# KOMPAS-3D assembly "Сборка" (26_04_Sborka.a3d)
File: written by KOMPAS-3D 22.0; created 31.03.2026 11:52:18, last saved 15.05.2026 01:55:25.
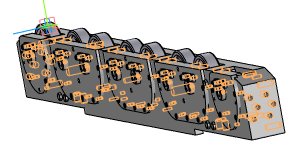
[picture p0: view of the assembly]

Document properties: Автор: taras; Полное имя файла: E:\test_kompas\all_v20\26_04_Sborka.a3d

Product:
- Component [detail]: Деталь  | qty 1  | pos. 2  | Масса: 261.985445; source file: ..\all_v22\3.1.8 дет.45 Балка(оригинал) (1).m3d
- Component [detail]: Деталь  | qty 1  | pos. 3  | Масса: 21.934157; Организация: TMK; Автор: TMK; source file: ..\all_v22\3.1.8  дет.46.2 Крышка балки (2).m3d
- Component [detail]: Деталь  | qty 1  | pos. 4  | Масса: 21.934157; Организация: TMK; Автор: TMK; source file: ..\all_v22\3.1.8  дет.46.2 Крышка балки (2).m3d
- Component [detail]: Деталь  | qty 1  | pos. 5  | Масса: 9.688835; source file: ..\all_v22\Крышка балки 1 окончательная (3).m3d
- Component [detail]: Деталь  | qty 1  | pos. 6  | Масса: 2.046242; Организация: TMK; Автор: TMK; source file: ..\all_v22\3.1.8 дет.74 Ось кронштейна крепления опорного ролика(новый блок) (1).m3d
- Component [detail]: Деталь  | qty 1  | pos. 7  | Масса: 2.046242; Организация: TMK; Автор: TMK; source file: ..\all_v22\3.1.8 дет.74 Ось кронштейна крепления опорного ролика(новый блок) (1).m3d
- Component [detail]: Деталь  | qty 1  | pos. 8  | Масса: 2.046242; Организация: TMK; Автор: TMK; source file: ..\all_v22\3.1.8 дет.74 Ось кронштейна крепления опорного ролика(новый блок) (1).m3d
- Component [detail]: Деталь  | qty 1  | pos. 12  | Масса: 19.948382; Автор: taras; source file: ..\all_v22\05.04 крышка200.m3d
- Component [detail]: Деталь  | qty 1  | pos. 13  | Масса: 2.046242; Организация: TMK; Автор: TMK; source file: ..\all_v22\3.1.8 дет.74 Ось кронштейна крепления опорного ролика(новый блок) (1).m3d
- Component [detail]: Деталь  | qty 1  | pos. 14  | Масса: 2.046242; Организация: TMK; Автор: TMK; source file: ..\all_v22\3.1.8 дет.74 Ось кронштейна крепления опорного ролика(новый блок) (1).m3d
- Component [detail]: Деталь  | qty 1  | pos. 15  | Масса: 9.688835; source file: ..\all_v22\Крышка балки 1 окончательная (3).m3d
- Component [detail]: Деталь  | qty 1  | pos. 16  | Масса: 2.046242; Организация: TMK; Автор: TMK; source file: ..\all_v22\3.1.8 дет.74 Ось кронштейна крепления опорного ролика(новый блок) (1).m3d
- Component [standard]: Винт М10-6gx20 ГОСТ 11738-84  | qty 31  | pos. 17  | Масса: 0.02351; Раздел спецификации: Стандартные изделия; Рассекать на разрезах: no
- Component [detail]: Деталь  | qty 1  | pos. 19  | Масса: 2.046242; Организация: TMK; Автор: TMK; source file: ..\all_v22\3.1.8 дет.74 Ось кронштейна крепления опорного ролика(новый блок) (1).m3d
- Component [detail]: Деталь  | qty 1  | pos. 20  | Масса: 2.046242; Организация: TMK; Автор: TMK; source file: ..\all_v22\3.1.8 дет.74 Ось кронштейна крепления опорного ролика(новый блок) (1).m3d
- Component [detail]: Деталь  | qty 1  | pos. 21  | Масса: 0.134151; Организация: TMK; Автор: TMK; source file: ..\all_v22\Planka_rigelnaya (1).m3d
- Component [detail]: Деталь  | qty 1  | pos. 22  | Масса: 0.134151; Организация: TMK; Автор: TMK; source file: ..\all_v22\Planka_rigelnaya (1).m3d
- Component [detail]: Деталь  | qty 1  | pos. 23  | Масса: 0.134151; Организация: TMK; Автор: TMK; source file: ..\all_v22\Planka_rigelnaya (1).m3d
- Component [detail]: Деталь  | qty 1  | pos. 24  | Масса: 0.134151; Организация: TMK; Автор: TMK; source file: ..\all_v22\Planka_rigelnaya (1).m3d
- Component [detail]: Деталь  | qty 1  | pos. 25  | Масса: 0.134151; Организация: TMK; Автор: TMK; source file: ..\all_v22\Planka_rigelnaya (1).m3d
- Component [detail]: Деталь  | qty 1  | pos. 26  | Масса: 0.134151; Организация: TMK; Автор: TMK; source file: ..\all_v22\Planka_rigelnaya (1).m3d
- Component [detail]: Деталь  | qty 1  | pos. 27  | Масса: 0.134151; Организация: TMK; Автор: TMK; source file: ..\all_v22\Planka_rigelnaya (1).m3d
- Component [detail]: Деталь  | qty 1  | pos. 28  | Масса: 0.134151; Организация: TMK; Автор: TMK; source file: ..\all_v22\Planka_rigelnaya (1).m3d
- Component [standard]: Подшипник 318 ГОСТ 8338-75  | qty 7  | pos. 29  | Масса: 4.954; Раздел спецификации: Стандартные изделия; additional columns: 318
- Component [standard]: Болт М16-6gx170 ГОСТ 7795-70  | qty 6  | pos. 30  | Масса: 0.2633; Раздел спецификации: Стандартные изделия; Рассекать на разрезах: no
- Component [standard]: Винт М12-6gx20 ГОСТ 11738-84  | qty 16  | pos. 31  | Масса: 0.03416; Раздел спецификации: Стандартные изделия; Рассекать на разрезах: no
- Part/product: Сборка
    Масса: 400.156123

Referenced files in E:\test_kompas\all_v22\: 3.1.8 дет.45 Балка(оригинал) (1).m3d, 3.1.8  дет.46.2 Крышка балки (2).m3d, Крышка балки 1 окончательная (3).m3d, 05.04 крышка200.m3d, 3.1.8 дет.74 Ось кронштейна крепления опорного ролика(новый блок) (1).m3d, Planka_rigelnaya (1).m3d
Referenced files in C:\Program Files\ASCON\KOMPAS-3D v22\Libs\PolynomLib\DATA\vault\Methods\Kompas\3D\: PLib_Screw_GOST_11738_1500.m3d, PLib_Bolt_1_900.m3d
Referenced files in C:\Program Files\ASCON\KOMPAS-3D v22\Libs\PolynomLib\DATA\vault\Methods\Kompas\3D\Bearings\8338_75\: PLib_Bearing_GOST_8338_75_712.a3d
Referenced files in C:\Program Files\ASCON\KOMPAS-3D v23 Study\Libs\PolynomLib\DATA\vault\Methods\Kompas\3D\: PLib_Screw_GOST_11738_1500.m3d, PLib_Bolt_1_900.m3d
Referenced files in C:\Program Files\ASCON\KOMPAS-3D v23 Study\Libs\PolynomLib\DATA\vault\Methods\Kompas\3D\Bearings\8338_75\: PLib_Bearing_GOST_8338_75_712.a3d
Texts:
  BOSimple***PART:419c87c2-70e2-98da-c2de-5eacb226740c***SHORTLOC:Root±30±20±10±80±10±GMC90[Нет;Без покрытия;Без указания материала;1,5;-;20;10]
  Крепежное изделие ГОСТ
  BOSimple***PART:61ab3e34-d848-86f0-c4aa-2b99c9f755c6***SHORTLOC:Root±Pac-16±Pac10±GMC20±GMC30±GMC10±GMC24[90;190;43]
  BOSimple***PART:9b7fe62b-1d30-3d6e-6be6-01a0e1891a36***SHORTLOC:Root±30±20±10±80±10±©{}30±©{BASE}130±190[Нет;Без покрытия;Без указания материала;170;16;22;2;-]
  BOSimple***PART:d3aa4c40-18a1-862e-ff95-3d42db175957***SHORTLOC:Root±30±20±10±80±10±GMC90[Нет;Без покрытия;Без указания материала;1,75;-;20;12]
  hole1
  hole2
  Радус под головкой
